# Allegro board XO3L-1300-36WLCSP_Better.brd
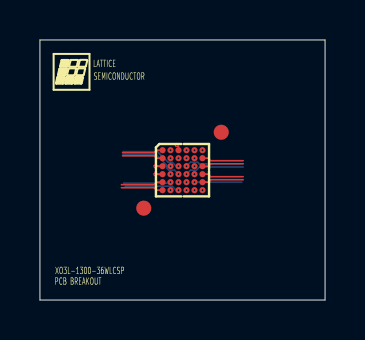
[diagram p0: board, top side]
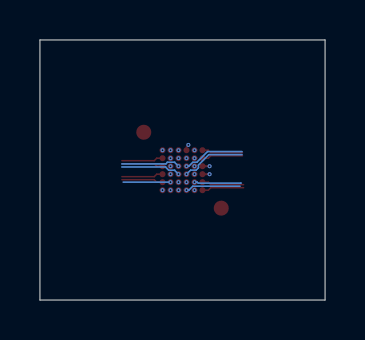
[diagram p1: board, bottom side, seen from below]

Outline 14.28 x 13.02 mm; copper layers: TOP, L2_SIG, L3_PWR, BOTTOM. Coordinates in mm from the lower left corner of the outline.
Outline path: 0,13.02 0,0 14.28,0 14.28,13.02 0,13.02

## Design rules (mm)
net group CDPB6: nets PB6C PB6D
net group CDPB20: nets PB20C PB20D
net group CDPL2: nets PL2C PL2D
net group CDPT10: nets PT10C PT10D
net group CDPT11: nets PT11C PT11D
net group CDPT12: nets PT12C PT12D
net group CDPT15: nets PT15C PT15D
net group CDPT17: nets PT17C PT17D
net group DIFFPAIR0: nets PT10A PT10B
net group DIFFPAIR1: nets PT12A PT12B
net group PB9: nets PB9A PB9B
net group PB11: nets PB11A PB11B
net group PL9: nets PL9A PL9B
net group PT9: nets PT9A PT9B

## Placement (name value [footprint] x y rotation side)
BGA  -  [BGA36N40P6X6_248X254X57B26N]  7.14 6.5 270 top
NOREF  -  []  0.41 10.21 0 top

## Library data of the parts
BGA = BGA36N40P6X6_248X254X57B26N

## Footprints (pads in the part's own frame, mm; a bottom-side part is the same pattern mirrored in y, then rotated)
BGA36N40P6X6_248X254X57B26N
  round 0.75 smd: (-1.9,1.94) (1.9,-1.94)
  round 0.305 smd: A1(-1,-1) A2(-1,-0.6) A3(-1,-0.2) A4(-1,0.2) A5(-1,0.6) A6(-1,1) B1(-0.6,-1) B2(-0.6,-0.6) B3(-0.6,-0.2) B4(-0.6,0.2) B5(-0.6,0.6) B6(-0.6,1) C1(-0.2,-1) C2(-0.2,-0.6) C3(-0.2,-0.2) C4(-0.2,0.2) C5(-0.2,0.6) C6(-0.2,1) D1(0.2,-1) D2(0.2,-0.6) D3(0.2,-0.2) D4(0.2,0.2) D5(0.2,0.6) D6(0.2,1) E1(0.6,-1) E2(0.6,-0.6) E3(0.6,-0.2) E4(0.6,0.2) E5(0.6,0.6) E6(0.6,1) F1(1,-1) F2(1,-0.6) F3(1,-0.2) F4(1,0.2) F5(1,0.6) F6(1,1)

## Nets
GND: BGA.C5 BGA.D1
VCC: BGA.C1 BGA.D5
VCCIO0: BGA.A3
VCCIO2: BGA.F2
VCCIO3: BGA.F6
PB4C: BGA.E5
PB6C: BGA.F5
PB6D: BGA.E4
PB9A: BGA.E3
PB9B: BGA.F4
PB11A: BGA.E2
PB11B: BGA.F3
PB20C: BGA.E1
PB20D: BGA.F1
PL2C: BGA.C6
PL2D: BGA.B6
PL9A: BGA.D6
PL9B: BGA.E6
PT9A: BGA.A6
PT9B: BGA.B5
PT10A: BGA.D4
PT10B: BGA.C4
PT10C: BGA.B4
PT10D: BGA.A5
PT11C: BGA.D3
PT11D: BGA.C3
PT12A: BGA.A4
PT12B: BGA.B3
PT12C: BGA.D2
PT12D: BGA.C2
PT15C: BGA.B2
PT15D: BGA.A2
PT17C: BGA.B1
PT17D: BGA.A1

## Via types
v1: diameter 0.203, hole 0.102, TOP to BOTTOM, 28 vias

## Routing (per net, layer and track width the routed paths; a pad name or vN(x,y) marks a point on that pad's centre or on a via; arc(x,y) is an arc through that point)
GND: length 0.4
  TOP w0.102: BGA.D1 v1(5.78,6.3)
  vias: v1(7.74,6.7)
VCC: length 0.4
  TOP w0.102: BGA.C1 v1(5.78,6.7)
  vias: v1(7.74,6.3)
VCCIO0: length 0.3
  TOP w0.076: v1(6.85,7.77) 6.94,7.67 BGA.A3
VCCIO2:
  vias: v1(6.54,5.5)
VCCIO3:
  vias: v1(8.14,5.5)
PB4C: length 2.4
  BOTTOM w0.076: v1(7.74,5.9) 10.11,5.9
PB6C: length 1.6
  L2_SIG w0.076: v1(7.74,5.5) 7.69,5.45 7.69,3.93
PB6D: length 2.1
  L2_SIG w0.076: 7.54,3.93 7.54,5.7 v1(7.34,5.9)
PB9A: length 2.1
  L2_SIG w0.076: 7.14,3.92 7.14,5.7 v1(6.94,5.9)
PB9B: length 1.6
  L2_SIG w0.076: 7.29,3.92 7.29,5.45 v1(7.34,5.5)
PB11A: length 2.4
  BOTTOM w0.076: 4.21,5.86 4.22,5.85 6.35,5.85 6.4,5.9 v1(6.54,5.9)
PB11B: length 2.8
  BOTTOM w0.076: 4.26,5.7 6.62,5.7 6.82,5.5 v1(6.94,5.5)
PB20C: length 2.1
  TOP w0.076: BGA.E1 5.85,5.9 5.73,5.78 4.08,5.78
PB20D: length 2.1
  TOP w0.076: BGA.F1 5.85,5.5 5.73,5.62 4.08,5.62
PL2C: length 2.1
  TOP w0.076: BGA.C6 8.43,6.7 8.55,6.82 10.18,6.82
PL2D: length 2.1
  TOP w0.076: 10.18,6.98 8.55,6.98 8.43,7.1 BGA.B6
PL9A: length 2.1
  TOP w0.076: 10.18,6.18 8.55,6.18 8.43,6.3 BGA.D6
PL9B: length 2.1
  TOP w0.076: 10.18,6.02 8.55,6.02 8.43,5.9 BGA.E6
PT9A: length 1.7
  L2_SIG w0.076: 8.09,9.18 8.09,7.55 v1(8.14,7.5)
PT9B: length 2.2
  L2_SIG w0.076: 7.94,9.18 7.94,7.3 v1(7.74,7.1)
PT10A: length 3
  BOTTOM w0.076: 10.18,6.66 7.99,6.66 7.83,6.5 7.54,6.5 v1(7.34,6.3)
PT10B: length 3
  BOTTOM w0.076: v1(7.34,6.7) 7.54,6.9 7.89,6.9 7.98,6.81 10.18,6.81
PT10C: length 2.2
  L2_SIG w0.076: v1(7.34,7.1) 7.54,7.3 7.54,9.2
PT10D: length 1.7
  L2_SIG w0.076: 7.69,9.2 7.69,7.55 v1(7.74,7.5)
PT11C: length 3.3
  BOTTOM w0.076: v1(6.94,6.3) 6.74,6.5 6.46,6.5 6.34,6.62 6.34,6.76 5.82,7.28 4.16,7.28
PT11D: length 3.1
  BOTTOM w0.076: v1(6.94,6.7) 6.82,6.7 6.62,6.9 6.42,6.9 5.88,7.43 4.16,7.43
PT12A: length 1.7
  L2_SIG w0.076: 7.29,9.19 7.29,7.55 v1(7.34,7.5)
PT12B: length 2.2
  L2_SIG w0.076: 7.14,9.19 7.14,7.3 v1(6.94,7.1)
PT12C: length 2.7
  L2_SIG w0.076: v1(6.54,6.3) 5.85,6.99 4.13,6.99
PT12D: length 2.6
  L2_SIG w0.076: v1(6.54,6.7) 6.36,6.7 5.91,7.14 4.13,7.14
PT15C: length 2.3
  L2_SIG w0.076: 6.11,9.19 6.11,7.39 6.28,7.22 6.42,7.22 v1(6.54,7.1)
PT15D: length 2.1
  L2_SIG w0.076: 6.26,9.19 6.26,7.45 6.34,7.38 6.42,7.38 v1(6.54,7.5)
PT17C: length 2.1
  TOP w0.076: 4.14,7.22 5.73,7.22 5.85,7.1 BGA.B1
PT17D: length 2.1
  TOP w0.076: 4.14,7.38 5.73,7.38 5.85,7.5 BGA.A1

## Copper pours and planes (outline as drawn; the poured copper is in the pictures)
GND on L3_PWR: 5.46,5.95 5.46,6.44 6.59,6.44 6.59,6.69 6.96,7.05 8.15,7.05 8.15,6.53 7.29,6.53 7.29,5.95
VCC on L3_PWR: 7.39,5.95 7.39,6.43 8.25,6.43 8.25,7.12 8.22,7.16 6.92,7.16 6.49,6.73 6.49,6.68 6.49,6.68 6.49,6.55 5.46,6.55 5.46,7.45 7.13,7.45 7.13,8.28 8.83,8.28 8.83,5.95
VCCIO0 on L3_PWR: 5.46,7.55 5.46,8.28 7.03,8.28 7.03,7.55
VCCIO2 on L3_PWR: 5.46,4.67 5.46,5.85 6.89,5.85 6.89,4.67
VCCIO3 on L3_PWR: 6.99,4.67 6.99,5.85 7.39,5.85 8.83,5.85 8.83,4.67

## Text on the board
User.Comments: ASP | CHRIS WEST | 07/01/14 | 07/14/14 | DWG NO: | XO3L-1300-36WLCSP | REVISION | 2.0 | SHEET | 1 | OF | XO3L-1300-36WLCSP PCB BREAKOUT | LATTICE SEMICONDUCTOR CORPORATION
Ref Des/Silkscreen Top: PCB BREAKOUT | XO3L-1300-36WLCSP | LATTICE | SEMICONDUCTOR
L3_PWR: A | B | C | D | E | F | 1 | 2 | 3 | 4 | 5 | 6
PAGE_OUTLINE: SPECIAL INSTRUCTIONS: | USE 1/2 OUNCE COPPER FOR BOTH INTERNAL AND EXTERNAL LAYERS | VIAS ARE TO BE NON-CONDUCTIVE EPOXY FILLED | PLANARIZE AT TOP AND BOTTOM | BOARD THICKNESS IS 62MILS | SIGNAL         (L2) | POWER/GND PLANE (L3) | PRIMARY SIDE   (L1) | SECONDARY SIDE (L4) | SECONDARY SILKSCREEN | SECONDARY SOLDERMASK | PRIMARY SOLDERMASK | PRIMARY SILKSCREEN | DESIGNED BY: | APPROVED BY: | SIGNATURES         DATE | REV | 1 | INITIAL RELEASE | ESCAPE VIA DRILL | TRACE WIDTH/SPACE | SPACE | ARRAY SIZE | ESCAPE VIA PAD | BGA LAND OPENING | PACKAGE SIZE | BGA LAND PAD | PITCH | DESCRIPTION | 2.487x2.541 | 0.0584 | 0.0762 | 0.1016 | 0.2032 | 0.30 | 6 X 6 | 0.40 | MM | 07/14/2014 | DATE | 12.00 | 15.748 | 2.3 | MILS | 8.00 | 4.00 | 3 | APPROVED | C. WEST | 4 LAYER STACKUP | PCB BREAKOUT DETAILS | REVISION
PLACE_BOUND_TOP: FIGURE | SIZE | 4.0 | DRILL CHART: TOP to BOTTOM | ALL UNITS ARE IN MILS | PLATED | QTY | 28
